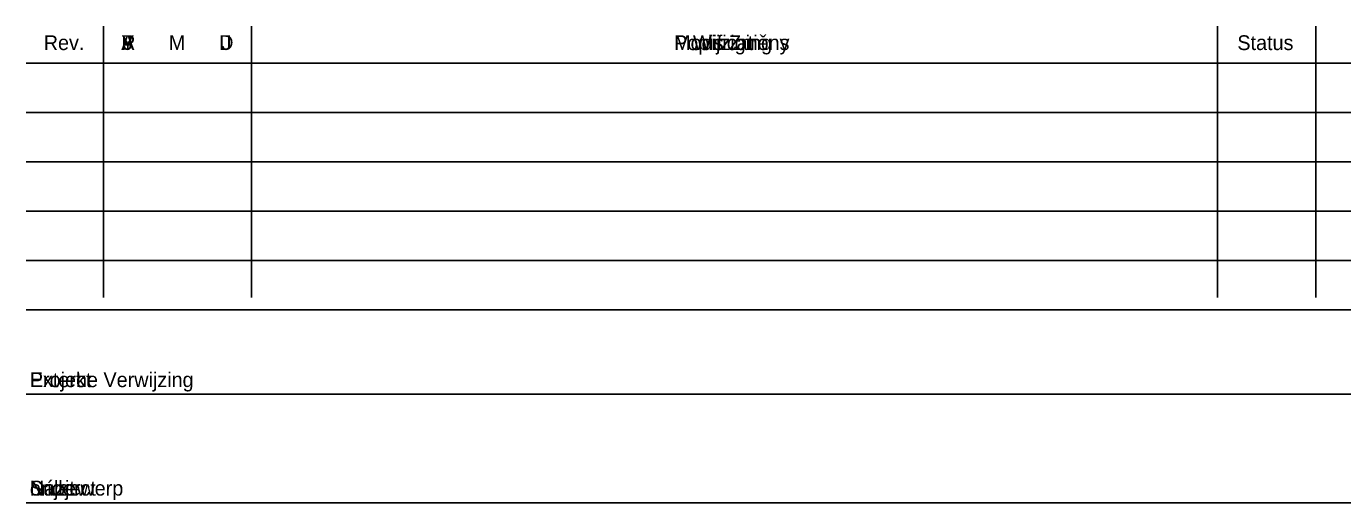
# Model space of a CAD drawing. Extents: x -760612 to 3170, y -975740 to 2995.
# Drawn here: x 727 to 2062, y 1100 to 1583 of the extents above; entities that cross this region are included whole.
import ezdxf

# ---------------------------------------------------------------- set-up
doc = ezdxf.new("R2010")
doc.units = 0
for name, color, linetype in [('Border', 7, 'Continuous'), ('Border_TextCZ', 7, 'Continuous'), ('Border_TextFR', 7, 'Continuous'), ('Border_TextNL', 7, 'Continuous'), ('Border_TextUK', 7, 'Continuous')]:
    doc.layers.add(name, color=color, linetype=linetype)

# ---------------------------------------------------------------- blocks, each defined once
blk = doc.blocks.new('A3coversheet_v03_CZ_1_1')
at = {"layer": 'Border'}
blk.add_line((2.1958, 1.5206), (4.0958, 1.5206), dxfattribs=at)
for points in [[(2.2742, 1.5581), (2.2742, 1.2831)], [(2.4242, 1.5581), (2.4242, 1.2831)], [(3.4042, 1.5581), (3.4042, 1.2831)], [(3.5042, 1.5581), (3.5042, 1.2831)], [(2.1958, 1.5206), (4.1042, 1.5206)], [(2.1958, 1.4706), (4.1042, 1.4706)], [(2.1958, 1.4206), (4.1042, 1.4206)], [(2.1958, 1.3706), (4.1042, 1.3706)], [(2.1958, 1.3206), (4.1042, 1.3206)], [(2.1958, 1.2706), (4.1042, 1.2706)], [(2.1958, 1.185), (4.1042, 1.185)], [(2.1958, 1.075), (4.1042, 1.075)]]:
    blk.add_lwpolyline(points, dxfattribs=at)
at = {"layer": 'Border_TextCZ'}
for s, p in [('Popis Změny', (2.853, 1.534)), ('Status', (3.4245, 1.534)), ('Rev.', (2.2135, 1.534)), ('R', (2.2921, 1.5341)), ('M', (2.3404, 1.5341)), ('D', (2.3915, 1.5341)), ('Projekt', (2.1994, 1.1922)), ('Název', (2.1994, 1.0822))]:
    blk.add_text(s, height=0.015, dxfattribs=at).set_placement(p)
at = {"layer": 'Border_TextFR'}
for s, p in [('Modifications', (2.853, 1.534)), ('Status', (3.4245, 1.534)), ('Rev.', (2.2135, 1.534)), ('A', (2.2921, 1.5341)), ('M', (2.3404, 1.5341)), ('J', (2.3939, 1.5341)), ('Projet', (2.1994, 1.1922)), ('Sujet', (2.1994, 1.0822))]:
    blk.add_text(s, height=0.015, dxfattribs=at).set_placement(p)
at = {"layer": 'Border_TextNL'}
for s, p in [('Wijziging', (2.8722, 1.534)), ('Status', (3.4245, 1.534)), ('Rev.', (2.2135, 1.534)), ('J', (2.2939, 1.5341)), ('M', (2.3404, 1.5341)), ('D', (2.3915, 1.5341)), ('Externe Verwijzing', (2.1994, 1.1922)), ('onderwerp', (2.1994, 1.0822))]:
    blk.add_text(s, height=0.015, dxfattribs=at).set_placement(p)
at = {"layer": 'Border_TextUK'}
for s, p in [('Modifications', (2.853, 1.534)), ('Status', (3.4245, 1.534)), ('Rev.', (2.2135, 1.534)), ('Y', (2.2921, 1.5341)), ('M', (2.3404, 1.5341)), ('D', (2.3915, 1.5341)), ('Project', (2.1994, 1.1922)), ('Subject', (2.1994, 1.0822))]:
    blk.add_text(s, height=0.015, dxfattribs=at).set_placement(p)

msp = doc.modelspace()

# ---------------------------------------------------------------- block references
at = {"layer": 'Border', "xscale": 1000.0000004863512, "yscale": 1000.0000004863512, "rotation": 4.518606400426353e-10}
msp.add_blockref('A3coversheet_v03_CZ_1_1', (-1469, 25), dxfattribs=at)

doc.saveas('drawing.dxf')
